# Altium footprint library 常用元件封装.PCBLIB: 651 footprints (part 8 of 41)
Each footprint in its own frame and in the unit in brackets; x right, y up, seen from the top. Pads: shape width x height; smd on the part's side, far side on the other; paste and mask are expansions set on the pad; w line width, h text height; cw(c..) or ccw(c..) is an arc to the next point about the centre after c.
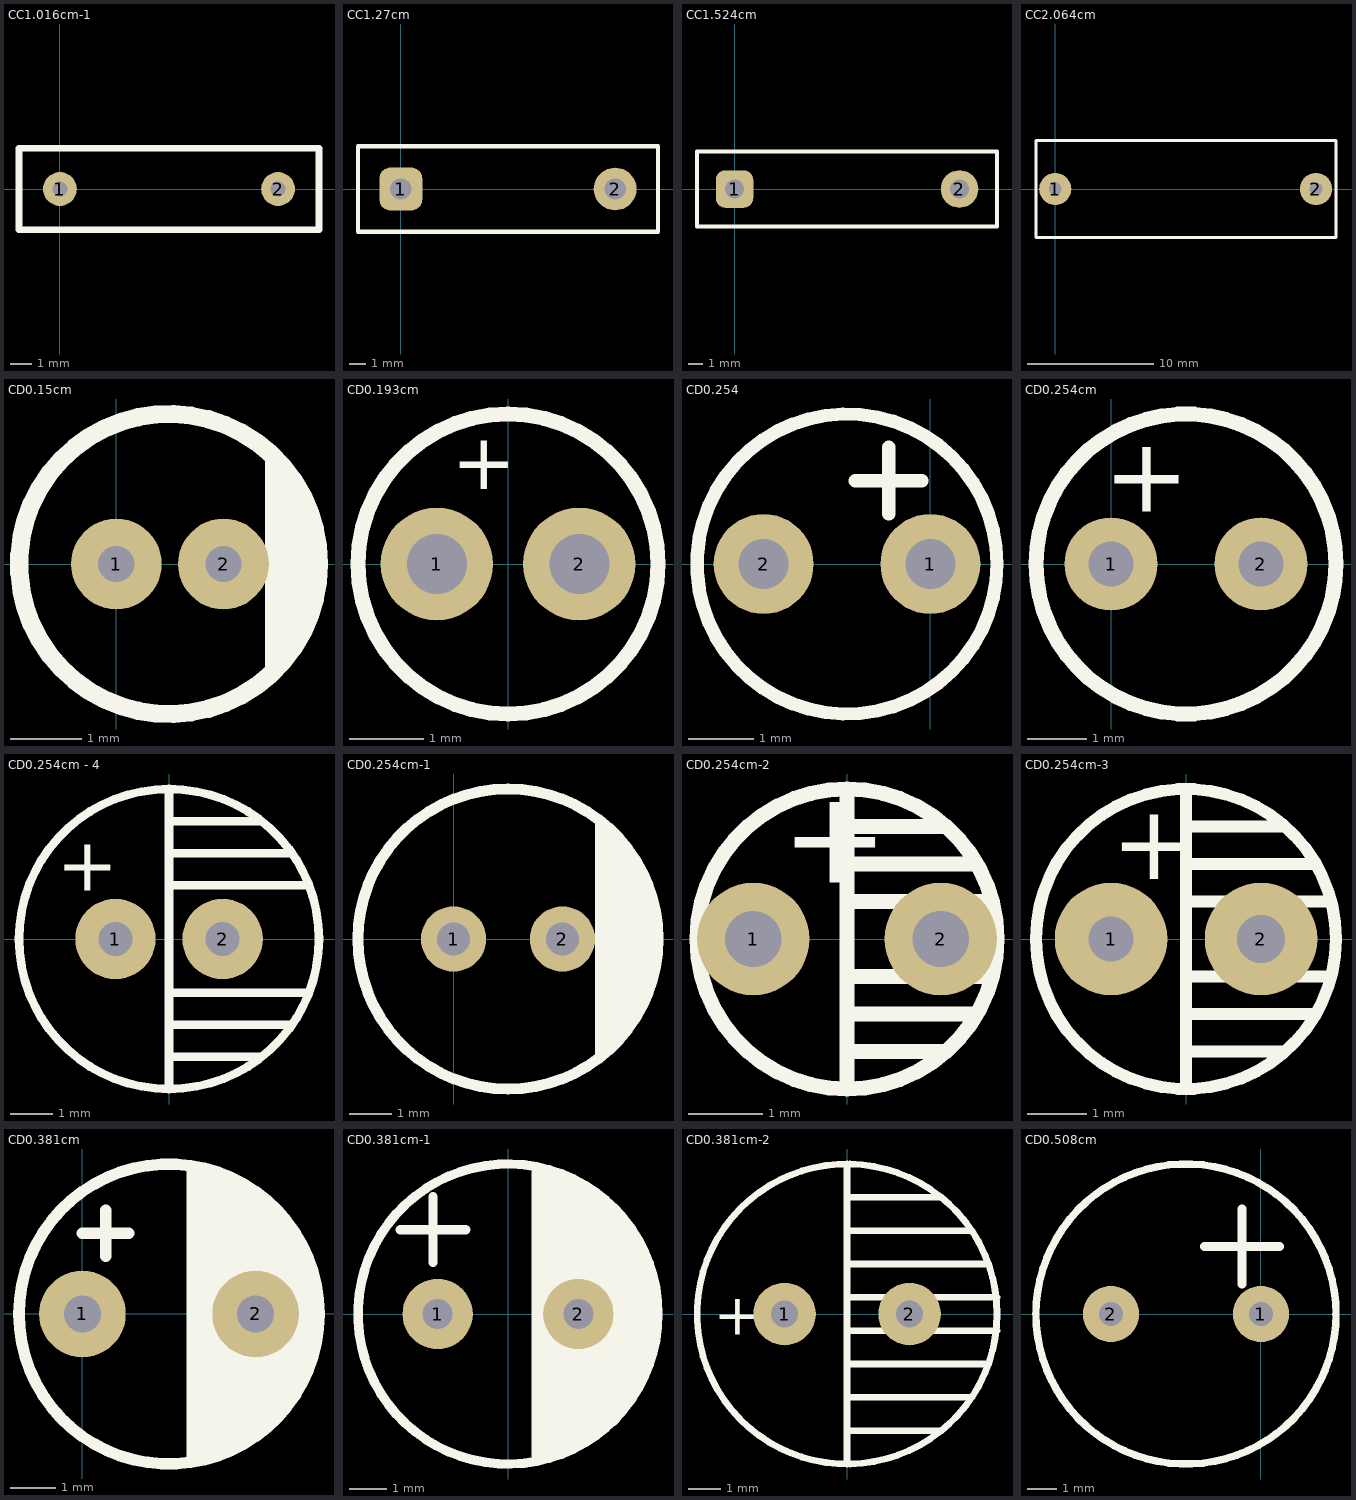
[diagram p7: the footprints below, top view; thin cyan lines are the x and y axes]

## CC1.016cm-1 [mil]
pads (2):
  round 62 hole 28: 1(0,0) 2(400,0)
TopOverlay:
  lines w12: -75,-75 -75,75 475,75 475,-75 -75,-75

## CC1.27cm [mil] "12.7mm"
pads (2):
  rrect50% 100x100 hole 50: 1(0,0)
  round 100 hole 50: 2(500,0)
TopOverlay:
  lines w10: -100,-100 0,-100 500,-100 600,-100 600,100 500,100 0,100 -100,100 -100,-100

## CC1.524cm [mil] "15.24mm"
pads (2):
  rrect50% 100x100 hole 50: 1(0,0)
  round 100 hole 50: 2(600,0)
TopOverlay:
  lines w10: -100,-100 0,-100 600,-100 700,-100 700,100 600,100 0,100 -100,100 -100,-100

## CC2.064cm [mm] "20.64mm"
pads (2):
  round 2.54 hole 1: 1(0,0) 2(20.64,0)
TopOverlay:
  lines w0.254: -1.524,-3.85 22.225,-3.85 22.225,3.85 -1.524,3.85 -1.524,-3.85

## CD0.15cm [mil] "4.3mmX1.5mm"
pads (2):
  round 50 hole 20: 1(0,0) 2(59.05,0)
TopOverlay:
  circle w10: c29,0 r82.68
  rectangle: 102,-26 110,24
  rectangle: 93,-43 103,44
  rectangle: 82,-59 94,58

## CD0.193cm [mil] "4.05mmX1.93mm"
pads (2):
  round 60 hole 32: 1(-38,0) 2(38,0)
TopOverlay:
  circle w8: c0,0 r80
  text "+" at -30,40 h30

## CD0.254 [mil] "4.58mmX2.54mm"
pads (2):
  round 60 hole 30: 1(0,0) 2(-100,0)
TopOverlay:
  circle w8: c-50,0 r90
  lines w8: -45,50 -5,50 ; -25,30 -25,70

## CD0.254cm [mil] "5.08mmX2.54mm"
pads (2):
  round 62 hole 30: 1(0,0) 2(100,0)
TopOverlay:
  circle w10: c50,0 r100
  text "+" at -5,35 h50

## CD0.254cm - 4 [mil] "7mmX2.54mm"
pads (2):
  round 75 hole 32: 1(-50,0) 2(50,0)
TopOverlay:
  circle w8: c0,0 r140
  lines w8: 0,-140 0,140 ; 0,-110 85,-110 ; 0,-80 115,-80 ; 0,-50 130,-50 ; 0,50 130,50 ; 0,80 115,80 ; 0,110 85,110
  text "+" at -105,45 h50

## CD0.254cm-1 [mil] "7mmX2.54mm"
pads (2):
  round 60 hole 30: 1(0,0) 2(100,0)
TopOverlay:
  circle w10: c50,0 r137.79
  rectangle: 175,-43 183,42
  rectangle: 165,-66 176,65
  rectangle: 154,-82 166,82
  rectangle: 142,-96 155,95
  rectangle: 130,-108 143,107

## CD0.254cm-2 [mil] "4mmX2.54mm"
pads (2):
  round 60 hole 30: 1(-50,0) 2(50,0)
TopOverlay:
  circle w8: c0,0 r80
  lines w8: 0,-80 0,80 ; 0,-60 50,-60 ; 0,-40 68,-40 ; 0,-20 75,-20 ; 0,20 75,20 ; 0,40 68,40 ; 0,60 50,60
  text "+" at -35,30 h50

## CD0.254cm-3 [mil] "5.08mmX2.54mm"
pads (2):
  round 75 hole 30: 1(-50,0)
  round 75 hole 32: 2(50,0)
TopOverlay:
  circle w8: c0,0 r100
  lines w8: 0,-95 0,95 ; 0,-75 65,-75 ; 0,-50 85,-50 ; 0,-25 95,-25 ; 0,25 95,25 ; 0,50 85,50 ; 0,75 65,75
  text "+" at -50,40 h50

## CD0.381cm [mil] "6.6mm3.81mm"
pads (2):
  round 75 hole 32: 1(0,0) 2(150,0)
TopOverlay:
  circle w10: c75,0 r130
  lines w10: 0,70 40,70 ; 20,50 20,90 ; 95,-125 95,125 ; 100,-125 100,125 ; 105,-120 105,125 ; 110,-120 110,120 ; 115,-115 115,120 ; 120,-115 120,120 ; 125,-110 125,115 ; 130,-110 130,115 ; 135,-105 135,110 ; 140,-105 140,110 ; 145,-100 145,105 ; 150,-100 150,105 ; 155,-95 155,100 ; 160,-90 160,95 ; 165,-85 165,90 ; 170,-85 170,85 ; 175,-80 175,80 ; 180,-65 180,70 ; 185,-70 185,65 ; 190,-45 190,50 ; 195,-50 195,40 ; 200,-20 200,30

## CD0.381cm-1 [mil] "8.1mm3.81mm"
pads (2):
  round 75 hole 32: 1(-75,0) 2(75,0)
TopOverlay:
  circle w10: c0,0 r160
  lines w10: -115,90 -45,90 ; -80,55 -80,125 ; 135,-80 135,80 ; 140,-70 140,65 ; 145,-60 145,55 ; 155,-30 155,25 ; 150,-45 150,45 150,-45
  lines w20: 35,-150 35,150 ; 50,-140 50,145 ; 65,-135 65,140 ; 80,-130 80,130 ; 95,-120 95,120 ; 110,-110 110,105 ; 125,-90 125,90

## CD0.381cm-2 [mil] "9.15mm3.81mm"
pads (2):
  round 75 hole 32: 1(-75,0) 2(75,0)
TopOverlay:
  circle w8: c0,0 r180
  lines w8: 0,-180 0,180 ; 0,-140 110,-140 ; 0,-100 150,-100 ; 0,-60 170,-60 ; 0,-20 180,-20 ; 0,20 180,20 ; 0,60 170,60 ; 0,100 150,100 ; 0,140 110,140
  text "+" at -160,-25 h50

## CD0.508cm [mil] "10.16mm5.08mm"
pads (2):
  round 75 hole 32: 1(0,0) 2(-200,0)
TopOverlay:
  circle w10: c-100,0 r200
  lines w12: -75,90 25,90 ; -25,40 -25,140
